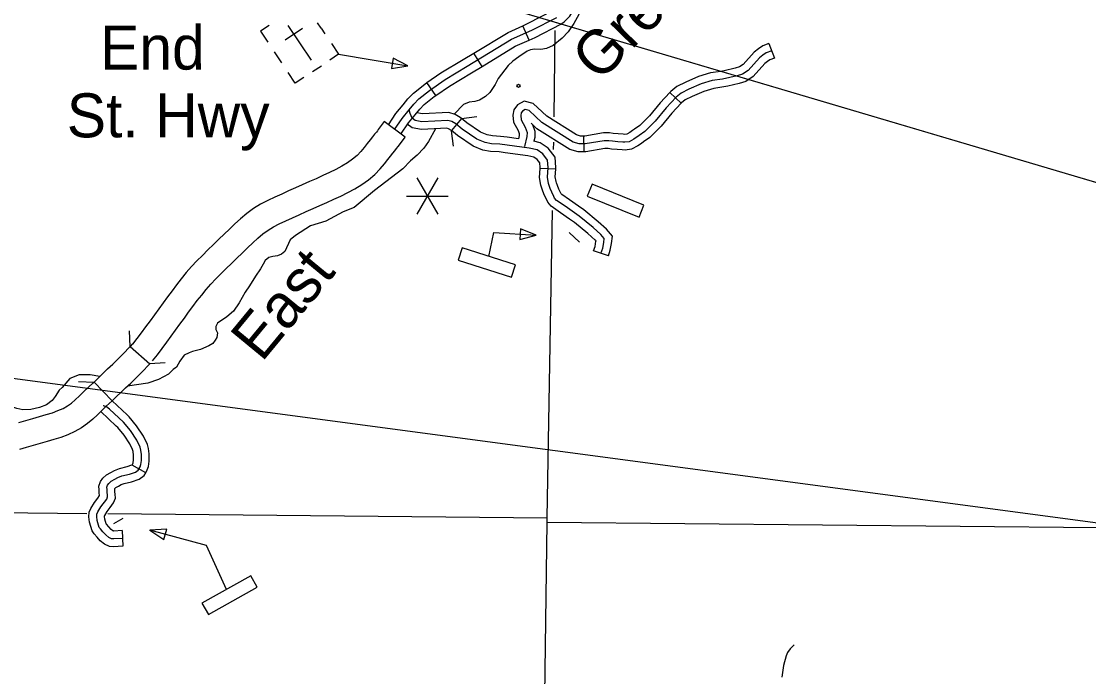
# Model space of a CAD drawing. Extents: x 0 to 3171, y 0 to 2059.
# Drawn here: x 1322.4 to 1493, y 655.3 to 760.1 of the extents above; entities that cross this region are included whole.
import ezdxf

# ---------------------------------------------------------------- set-up
doc = ezdxf.new("R2010")
doc.units = 0
for name, color, linetype in [('Default', 7, 'Continuous'), ('Level 10', 7, 'Continuous'), ('Level 32', 7, 'Continuous'), ('Level 35', 7, 'Continuous'), ('Level 37', 7, 'Continuous'), ('Level 38', 7, 'Continuous'), ('Level 4', 7, 'Continuous'), ('Level 41', 7, 'Continuous'), ('Level 45', 7, 'Continuous'), ('Level 48', 7, 'Continuous'), ('Level 5', 7, 'Continuous'), ('Level 57', 7, 'Continuous')]:
    doc.layers.add(name, color=color, linetype=linetype)

msp = doc.modelspace()

# ---------------------------------------------------------------- linework, layer by layer
at = {"layer": 'Default'}
for p in [(979.56, 748.65), (1029.42, 741.99)]:
    msp.add_line(p, (1637.4, 660.79), dxfattribs=at)
for points in [[(641.57, 882.9), (992.89, 882.9), (1640.89, 690.88)], [(1029.42, 872.07), (1640.89, 690.88)]]:
    msp.add_lwpolyline(points, dxfattribs=at)
at = {"layer": 'Level 10'}
for points in [[(1383.71, 741.57), (1380.37, 744.06), (1379.43, 742.8), (1379.29, 742.6), (1379.13, 742.4), (1378.84, 742.06), (1378.49, 741.62), (1378.11, 741.14), (1377.66, 740.57), (1377.16, 739.91), (1376.63, 739.27), (1376.03, 738.65), (1375.31, 738.04), (1374.51, 737.47), (1373.62, 736.93), (1372.64, 736.42), (1371.63, 735.91), (1370.57, 735.43), (1369.51, 734.94), (1368.41, 734.47), (1367.29, 733.97), (1366.2, 733.47), (1365.09, 732.98), (1363.99, 732.48), (1362.89, 731.98), (1361.76, 731.45), (1360.61, 730.86), (1359.48, 730.16), (1358.41, 729.38), (1357.42, 728.54), (1356.52, 727.7), (1355.66, 726.88), (1354.81, 726.06), (1353.95, 725.24), (1353.08, 724.4), (1352.2, 723.55), (1351.32, 722.68), (1350.45, 721.79), (1349.59, 720.88), (1348.73, 719.91), (1347.94, 718.92), (1347.18, 717.96), (1346.46, 716.99), (1345.76, 716.04), (1345.07, 715.09), (1344.36, 714.13), (1343.67, 713.17), (1342.95, 712.21), (1342.24, 711.22), (1341.55, 710.27), (1340.85, 709.37), (1340.12, 708.47)], [(1343.34, 705.82), (1344.12, 706.78), (1344.88, 707.78), (1345.61, 708.77), (1346.31, 709.74), (1347.03, 710.7), (1347.73, 711.67), (1348.43, 712.62), (1349.12, 713.58), (1349.81, 714.51), (1350.49, 715.43), (1351.21, 716.33), (1351.91, 717.22), (1352.66, 718.05), (1353.46, 718.9), (1354.28, 719.74), (1355.12, 720.58), (1355.97, 721.4), (1356.84, 722.23), (1357.7, 723.05), (1358.55, 723.87), (1359.38, 724.67), (1360.19, 725.42), (1360.99, 726.1), (1361.81, 726.7), (1362.67, 727.23), (1363.6, 727.72), (1364.63, 728.2), (1365.71, 728.69), (1366.8, 729.18), (1367.9, 729.67), (1369, 730.17), (1370.08, 730.65), (1371.2, 731.13), (1372.31, 731.64), (1373.43, 732.15), (1374.55, 732.71), (1375.67, 733.31), (1376.8, 733.99), (1377.87, 734.75), (1378.86, 735.6), (1379.74, 736.49), (1380.42, 737.32), (1380.95, 738), (1381.38, 738.56), (1381.76, 739.03), (1382.06, 739.42), (1382.35, 739.76), (1382.63, 740.1), (1382.8, 740.35), (1383.71, 741.57)], [(1334, 702.42), (1336.17, 704.5), (1336.99, 705.28), (1337.81, 706.06), (1338.62, 706.86), (1339.79, 708.11)], [(1340.17, 708.53), (1339.79, 708.11), (1342.9, 705.32)], [(1336.87, 699.41), (1339.04, 701.48), (1339.86, 702.26), (1340.71, 703.07), (1341.58, 703.93), (1342.9, 705.32)], [(1322, 695.93), (1323.11, 696.25), (1324.21, 696.56), (1325.3, 696.88), (1326.36, 697.2), (1327.34, 697.51), (1328.23, 697.84), (1329.04, 698.2), (1329.74, 698.6), (1330.37, 699.05), (1331, 699.58), (1331.66, 700.2), (1332.36, 700.88), (1333.1, 701.58), (1333.84, 702.27), (1334, 702.42), (1336.87, 699.41)], [(1336.87, 699.41), (1335.96, 698.55), (1335.24, 697.87), (1334.53, 697.19), (1333.78, 696.48), (1332.94, 695.76), (1331.97, 695.07), (1330.91, 694.48), (1329.82, 693.99), (1328.7, 693.57), (1327.59, 693.22), (1326.48, 692.88), (1325.37, 692.56), (1324.25, 692.24), (1323.16, 691.93), (1322.09, 691.62)]]:
    msp.add_lwpolyline(points, dxfattribs=at)
at = {"layer": 'Level 32'}
for p, q in [((1403.55, 757.11), (1402.52, 759.39)), ((1396.01, 752.9), (1394.72, 755.04)), ((1388.64, 748.25), (1387.21, 750.3))]:
    msp.add_line(p, q, dxfattribs=at)
for points in [[(1402.52, 759.39), (1403.4, 759.79), (1407.34, 761.82), (1407.55, 761.96), (1408.06, 762.47), (1408.46, 763.16), (1408.6, 763.68)], [(1403.55, 757.11), (1404.49, 757.54), (1408.63, 759.67), (1409.15, 760.03), (1410.06, 760.93), (1410.78, 762.18), (1411.01, 763)], [(1382.04, 742.82), (1383.24, 744.59), (1384.36, 745.96), (1385.12, 746.87), (1385.9, 747.71), (1387.64, 749.07), (1390.12, 750.8), (1393.66, 752.94), (1400.75, 757.23), (1403.95, 758.67), (1407.99, 760.74)], [(1394.72, 755.04), (1400.17, 758.33), (1402.52, 759.39)], [(1396.01, 752.9), (1401.33, 756.12), (1403.55, 757.11)], [(1387.21, 750.3), (1389.44, 751.85), (1393.02, 754.01), (1394.72, 755.04)], [(1388.64, 748.25), (1390.8, 749.75), (1394.31, 751.87), (1396.01, 752.9)], [(1381.04, 743.57), (1382.23, 745.34), (1383.4, 746.75), (1384.18, 747.7), (1385.05, 748.63), (1386.89, 750.08), (1387.21, 750.3)], [(1383.05, 742.07), (1384.24, 743.85), (1385.32, 745.16), (1386.07, 746.05), (1386.75, 746.79), (1388.38, 748.07), (1388.64, 748.25)]]:
    msp.add_lwpolyline(points, dxfattribs=at)
at = {"layer": 'Level 35'}
for points in [[(1414.27, 764.34), (1413.69, 763.62), (1413.14, 763.25), (1412.36, 762.77), (1410.67, 759.74), (1409.8, 758.45), (1408.81, 757.41), (1407.38, 756.24), (1406.33, 755.75), (1405.41, 755.62), (1404.38, 755.63), (1403.75, 755.54), (1403.25, 755.31), (1401.91, 754.43), (1400.95, 753.71), (1400.18, 753.06)], [(1400.18, 753.06), (1398.6, 750.96), (1398.13, 750.01), (1397.25, 748.72), (1396.56, 748.08), (1395.63, 747.49), (1394.89, 747.27), (1393.94, 747.16), (1393.05, 746.8), (1391.56, 745.27)], [(1388.57, 742.91), (1387.45, 740.9), (1386.73, 739.83), (1385.64, 738.72), (1384.56, 737.79), (1383.36, 736.54), (1378.8, 733.05), (1375.57, 730.31)], [(1375.57, 730.31), (1373.8, 729.66), (1371.03, 728.13), (1368.62, 727.4), (1366.22, 725.86), (1365.37, 725.15), (1364.5, 723.32), (1363.97, 722.87), (1363.34, 722.59), (1362.56, 722.47), (1361.94, 722.32), (1361.37, 721.88), (1361.02, 721.29), (1360.58, 720.53), (1359.78, 719.35), (1358.86, 717.8), (1358.13, 716.8), (1357.2, 715.1), (1356.3, 713.77), (1355.2, 712.87), (1353.71, 711.84), (1353.47, 711.31), (1353.46, 710.81), (1353.72, 710.26), (1353.6, 709.56), (1353.37, 709.13), (1352.97, 708.6), (1352.32, 708.18), (1351, 707.63), (1349.73, 707.32), (1349.18, 707.09), (1348.41, 706.73), (1347.71, 705.74), (1347.2, 704.78), (1346.67, 704.41), (1345.88, 703.67), (1344.32, 702.8), (1342.6, 702.22), (1339.36, 701.78)], [(1334.93, 703.32), (1333.4, 703.57), (1331.62, 703.55), (1330.12, 702.96), (1328.9, 701.54), (1328.43, 701.12), (1327.77, 700.08), (1327.32, 699.45), (1326.4, 698.75), (1325.27, 698.34), (1323.87, 698.02), (1322.64, 697.99), (1321.66, 698.18), (1320.8, 698.43), (1319.95, 698.4), (1317.03, 697.42), (1315.57, 696.06), (1312.88, 693.47)], [(1445.93, 660.38), (1445.27, 659.74), (1444.84, 659.13), (1444.63, 658.6), (1444.22, 657.05), (1443.95, 655.21)]]:
    msp.add_lwpolyline(points, dxfattribs=at)
at = {"layer": 'Level 37'}
for points in [[(1339.79, 708.11), (1339.66, 710.6)], [(1345.39, 705.46), (1342.9, 705.32)], [(1331.5, 702.48), (1334, 702.42)], [(1336.87, 699.41), (1336.87, 699.41)]]:
    msp.add_lwpolyline(points, dxfattribs=at)
at = {"layer": 'Level 38'}
for points in [[(1392.72, 744.58), (1395.2, 744.87)], [(1391.45, 740.14), (1391.16, 742.62)]]:
    msp.add_lwpolyline(points, dxfattribs=at)
at = {"layer": 'Level 4'}
for points in [[(1407.52, 744.81), (1407.71, 758.64)], [(1407.45, 739.6), (1407.47, 740.79)], [(1405.23, 592.96), (1406.43, 680), (1406.44, 680.69), (1407.28, 729.83)]]:
    msp.add_lwpolyline(points, dxfattribs=at)
at = {"layer": 'Level 45'}
for p, q in [((1441.88, 756.56), (1442.78, 754.23)), ((1426.02, 748.71), (1427.84, 747)), ((1392.73, 744.57), (1391.15, 742.63)), ((1412.25, 741.75), (1412.27, 739.25)), ((1407.79, 736.44), (1405.3, 736.57)), ((1416.22, 722.59), (1413.85, 723.39)), ((1342.27, 687.91), (1340.07, 689.11)), ((1338.47, 678.66), (1338.61, 676.16))]:
    msp.add_line(p, q, dxfattribs=at)
for points in [[(1441.88, 756.56), (1440.89, 756.17), (1440.19, 755.73), (1439.5, 755.17), (1437.73, 753.19), (1437.15, 752.81), (1436.46, 752.61), (1434.73, 752.19)], [(1442.33, 755.39), (1441.45, 755.05), (1440.92, 754.72), (1440.36, 754.26), (1438.55, 752.23), (1437.67, 751.66), (1436.78, 751.4), (1434.44, 750.84), (1432.78, 750.62), (1431.03, 750.09), (1429.09, 749.24), (1427.83, 748.62), (1427.05, 747.98), (1425.42, 746.25), (1423.71, 744.16), (1422.03, 742.48), (1421.12, 741.84), (1420.29, 741.27), (1419.54, 740.85), (1418.84, 740.77), (1418.51, 740.79), (1417.71, 740.84), (1416.85, 740.92), (1416.29, 741.01), (1415.54, 741), (1412.52, 740.5), (1411.55, 740.49), (1410.58, 740.78), (1405.58, 743.93), (1403.57, 745.85), (1402.92, 745.99), (1402.49, 745.76), (1402.26, 745.46), (1402.2, 745.06), (1402.29, 744.36), (1402.92, 743.18), (1403.21, 742.35), (1403.18, 741.68), (1402.82, 740.1)], [(1442.78, 754.23), (1442.02, 753.93), (1441.65, 753.7), (1441.23, 753.35), (1439.37, 751.28), (1438.2, 750.51), (1437.1, 750.19), (1435.31, 749.76)], [(1434.73, 752.19), (1434.21, 752.07), (1432.51, 751.85), (1430.6, 751.26), (1428.57, 750.38), (1427.15, 749.68), (1426.2, 748.9), (1426.02, 748.71)], [(1435.31, 749.76), (1434.66, 749.61), (1433.05, 749.39), (1431.46, 748.91), (1429.62, 748.11), (1428.51, 747.56), (1427.91, 747.07), (1427.84, 747)], [(1405.6, 745.64), (1404.18, 746.99), (1402.73, 747.32), (1401.66, 746.73), (1401.08, 745.96), (1400.94, 745.08), (1401.07, 743.97), (1401.78, 742.67), (1401.95, 742.16), (1401.94, 741.85), (1401.82, 741.33)], [(1426.02, 748.71), (1424.48, 747.08), (1422.78, 745), (1421.22, 743.44), (1420.41, 742.87), (1420.08, 742.65)], [(1383.15, 745.62), (1383.15, 745.64)], [(1415.03, 722.99), (1415.31, 723.8), (1415.47, 724.74), (1415.54, 725.35), (1415.02, 725.99), (1413.77, 727.11), (1411.54, 728.95), (1409.29, 730.52), (1407.91, 731.46), (1407.6, 731.85), (1407.49, 732.07), (1407.17, 732.77), (1406.92, 733.38), (1406.74, 733.85), (1406.62, 734.19), (1406.48, 735.19), (1406.56, 736.73), (1406.48, 737.91), (1405.72, 738.92), (1404.81, 739.53), (1403.56, 739.84), (1398.87, 740.46), (1397.54, 740.53), (1396.5, 740.73), (1395.2, 741.27), (1392.84, 742.87), (1391.83, 743.69), (1391.19, 744.07), (1390.56, 744.27), (1386.41, 744.05), (1385.35, 744.25), (1384.86, 744.61), (1384.52, 745.34), (1384.36, 745.96)], [(1392.73, 744.57), (1392.54, 744.72), (1391.7, 745.22), (1390.72, 745.53), (1386.49, 745.31), (1385.58, 745.47)], [(1412.25, 741.75), (1411.73, 741.74), (1411.1, 741.93), (1406.35, 744.92), (1405.6, 745.64)], [(1427.84, 747), (1426.36, 745.43), (1424.64, 743.32), (1422.83, 741.52), (1421.83, 740.81), (1421.49, 740.58)], [(1400.01, 741.57), (1398.99, 741.7), (1397.69, 741.78), (1396.85, 741.93), (1395.79, 742.37), (1393.59, 743.87), (1392.73, 744.57)], [(1412.27, 739.25), (1411.38, 739.24), (1410.06, 739.63), (1404.8, 742.94), (1403.87, 743.83)], [(1391.15, 742.63), (1391.11, 742.67), (1390.68, 742.92), (1390.4, 743.01), (1386.33, 742.8), (1384.84, 743.07), (1384.07, 743.64)], [(1399.69, 739.09), (1398.76, 739.21), (1397.39, 739.29), (1396.14, 739.52), (1394.6, 740.16), (1392.1, 741.86), (1391.15, 742.63)], [(1404.09, 743.62), (1404.47, 742.53), (1404.43, 741.51), (1404.3, 740.95)], [(1420.08, 742.65), (1419.63, 742.34), (1419.14, 742.06), (1418.81, 742.02), (1418.6, 742.04), (1417.8, 742.09), (1417, 742.16), (1416.38, 742.26), (1415.43, 742.25), (1412.42, 741.75), (1412.25, 741.75)], [(1401.82, 741.33), (1400.01, 741.57)], [(1407.79, 736.44), (1407.81, 736.74), (1407.7, 738.36), (1406.6, 739.84), (1405.32, 740.7), (1404.3, 740.95)], [(1421.49, 740.58), (1420.94, 740.21), (1419.93, 739.64), (1418.87, 739.51), (1418.43, 739.54), (1417.61, 739.6), (1416.69, 739.68), (1416.2, 739.76), (1415.65, 739.75), (1412.63, 739.25), (1412.27, 739.25)], [(1405.3, 736.57), (1405.3, 736.72), (1405.26, 737.46), (1404.85, 738), (1404.3, 738.37), (1403.33, 738.61), (1399.69, 739.09)], [(1410.02, 728.48), (1408.58, 729.49), (1407.05, 730.53), (1406.53, 731.18), (1406.36, 731.54), (1406.02, 732.27), (1405.75, 732.93), (1405.57, 733.42), (1405.4, 733.89), (1405.22, 735.14), (1405.3, 736.57)], [(1411.46, 730.53), (1410, 731.55), (1408.77, 732.39), (1408.67, 732.52), (1408.63, 732.6), (1408.31, 733.27), (1408.08, 733.83), (1407.92, 734.28), (1407.84, 734.5), (1407.73, 735.25), (1407.79, 736.44)], [(1416.22, 722.59), (1416.52, 723.5), (1416.71, 724.56), (1416.85, 725.72), (1415.93, 726.86), (1414.58, 728.06), (1412.29, 729.94), (1411.46, 730.53)], [(1413.85, 723.39), (1414.09, 724.11), (1414.23, 724.92), (1414.24, 724.98), (1414.11, 725.13), (1412.95, 726.17), (1410.78, 727.95), (1410.02, 728.48)], [(1338.54, 677.41), (1337.14, 677.33), (1336.78, 677.36), (1336.34, 677.55), (1335.86, 677.95), (1335.42, 678.44), (1335.01, 678.92), (1334.82, 679.17), (1334.49, 680.25), (1334.42, 680.9), (1334.45, 681.29), (1334.59, 681.63), (1335.09, 682.43), (1336.02, 683.69), (1336.15, 684.03), (1336.13, 684.37), (1336.09, 684.76), (1336.07, 685.23), (1336.04, 685.6), (1336.15, 685.93), (1336.34, 686.18), (1336.73, 686.55), (1337.3, 686.87), (1337.81, 687.15), (1338.44, 687.4), (1339.64, 687.67), (1340.63, 688.02), (1341.07, 688.32), (1341.35, 688.84), (1341.46, 689.21), (1341.57, 689.87), (1341.56, 690.82), (1341.46, 691.54), (1341.35, 692.01), (1340.83, 693.14), (1339.8, 694.67), (1338.69, 696.01), (1336.48, 698.09), (1335.97, 698.44), (1335.51, 698.61), (1335.44, 698.61)], [(1339.27, 697.18), (1336.89, 699.43)], [(1337.56, 695.36), (1335.07, 697.71)], [(1342.27, 687.91), (1342.51, 688.36), (1342.68, 688.92), (1342.83, 689.78), (1342.81, 690.92), (1342.7, 691.76), (1342.54, 692.42), (1341.92, 693.75), (1340.8, 695.42), (1339.6, 696.87), (1339.27, 697.18)], [(1340.07, 689.11), (1340.19, 689.33), (1340.24, 689.49), (1340.32, 689.97), (1340.31, 690.73), (1340.23, 691.31), (1340.17, 691.6), (1339.74, 692.52), (1338.8, 693.92), (1337.78, 695.15), (1337.56, 695.36)], [(1334.59, 683.86), (1334.89, 684.25), (1334.88, 684.27), (1334.84, 684.67), (1334.82, 685.15), (1334.77, 685.74), (1335.03, 686.52), (1335.41, 687.03), (1336, 687.57), (1336.69, 687.96), (1337.27, 688.28), (1338.07, 688.6), (1339.3, 688.88), (1340.06, 689.15), (1340.12, 689.19), (1340.07, 689.11)], [(1336.59, 682.36), (1337.13, 683.09), (1337.41, 683.84), (1337.38, 684.46), (1337.34, 684.85), (1337.32, 685.32), (1337.31, 685.38), (1337.47, 685.53), (1337.91, 685.77), (1338.35, 686.02), (1338.81, 686.21), (1339.99, 686.47), (1341.19, 686.9), (1342.02, 687.46), (1342.27, 687.91)], [(1338.61, 676.16), (1337.13, 676.08), (1336.47, 676.13), (1335.68, 676.47), (1334.99, 677.04), (1334.48, 677.61), (1334.03, 678.14), (1333.69, 678.6), (1333.25, 680), (1333.17, 680.88), (1333.21, 681.59), (1333.48, 682.2), (1334.05, 683.14), (1334.59, 683.86)], [(1338.47, 678.66), (1337.16, 678.58), (1337.09, 678.59), (1337, 678.63), (1336.73, 678.85), (1336.36, 679.26), (1335.99, 679.7), (1335.95, 679.75), (1335.72, 680.5), (1335.68, 680.92), (1335.68, 681), (1335.7, 681.05), (1336.12, 681.73), (1336.59, 682.36)]]:
    msp.add_lwpolyline(points, dxfattribs=at)
at = {"layer": 'Level 48'}
for p, q in [((1388.93, 735.06), (1385.59, 729.28)), ((1385.59, 735.06), (1388.93, 729.28)), ((1383.93, 732.17), (1390.59, 732.17))]:
    msp.add_line(p, q, dxfattribs=at)
at = {"layer": 'Level 5'}
for points in [[(1318.69, 681.53), (1332.85, 681.4)], [(1336.22, 681.37), (1406.44, 680.69)], [(1406.43, 680), (1494.45, 679.13)]]:
    msp.add_lwpolyline(points, dxfattribs=at)
at = {"layer": 'Level 57'}
for p, q in [((1364.99, 759.44), (1368.7, 753.91)), ((1370.31, 758.99), (1369.73, 759.85)), ((1364.53, 757.13), (1367.31, 758.99)), ((1370.31, 758.99), (1370.89, 758.12)), ((1366.84, 756.67), (1366.84, 756.67)), ((1366.84, 756.67), (1366.84, 756.67)), ((1362.81, 755.21), (1363.97, 753.48)), ((1368.94, 752.06), (1370.33, 752.99)), ((1413.6, 734.07), (1412.81, 732.15)), ((1421.9, 730.69), (1413.6, 734.07)), ((1412.81, 732.15), (1421.11, 728.76)), ((1421.11, 728.76), (1421.9, 730.69)), ((1392.85, 723.87), (1392.22, 721.89)), ((1401.39, 721.16), (1392.85, 723.87)), ((1392.22, 721.89), (1400.75, 719.18)), ((1400.75, 719.18), (1401.39, 721.16)), ((1359.06, 671.42), (1351.25, 667.03)), ((1360.08, 669.6), (1359.06, 671.42)), ((1352.27, 665.22), (1360.08, 669.6)), ((1351.25, 667.03), (1352.27, 665.22))]:
    msp.add_line(p, q, dxfattribs=at)
for points in [[(1361.98, 759.44), (1360.6, 758.51), (1361.76, 756.78)], [(1371.93, 756.57), (1373.09, 754.84), (1371.7, 753.91)], [(1373.09, 754.84), (1384.18, 752.98)], [(1367.55, 751.13), (1366.17, 750.2), (1365.01, 751.93)], [(1397.12, 722.52), (1397.91, 726.31), (1404.65, 725.93)], [(1409.95, 726.31), (1411.58, 724.77)], [(1337.14, 679.79), (1338.65, 680.63)], [(1355.15, 669.22), (1351.95, 676.25), (1342.92, 678.73)]]:
    msp.add_lwpolyline(points, dxfattribs=at)
for points in [[(1381.81, 754.24), (1381.53, 752.56), (1384.18, 752.98)], [(1402.15, 726.92), (1402.06, 725.23), (1404.65, 725.93)], [(1345.16, 677.23), (1345.61, 678.87), (1342.92, 678.73)]]:
    msp.add_lwpolyline(points, close=True, dxfattribs=at)
msp.add_circle((1401.84, 749.79), 0.25, dxfattribs=at)

# ---------------------------------------------------------------- texts
at = {"layer": 'Level 35'}
for s, rotation, p in [('Greasy', 45.5399, (1414.78, 750.22)), ('East', 50.4774, (1360.79, 705.44))]:
    msp.add_text(s, height=7.04, rotation=rotation, dxfattribs=at).set_placement(p)
at = {"layer": 'Level 41'}
for s, p in [('End', (1334.95, 752.39)), ('St. Hwy', (1329.64, 741.55))]:
    msp.add_text(s, height=7.04, dxfattribs=at).set_placement(p)

doc.saveas('drawing.dxf')
